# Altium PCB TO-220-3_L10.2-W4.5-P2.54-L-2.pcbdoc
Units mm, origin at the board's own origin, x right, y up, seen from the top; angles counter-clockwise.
Board outline 22.92 x 17.77 mm, 2 copper layers (Top Layer, Bottom Layer), stack 0 mm thick; 1 components, 0 nets, 3 pads, 0 vias.
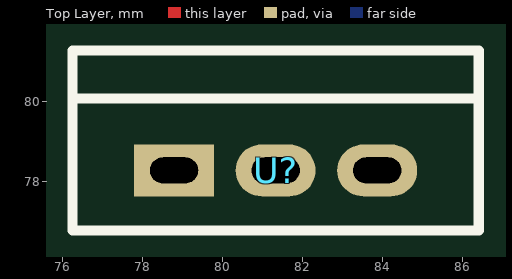
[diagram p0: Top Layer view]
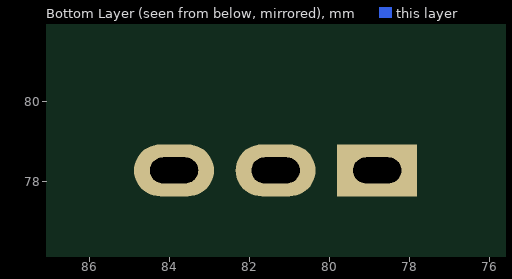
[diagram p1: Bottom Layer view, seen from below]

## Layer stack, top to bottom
Top Layer: signal copper (thickness not stored)
Bottom Layer: signal copper (thickness not stored)

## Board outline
92.77,69.85 69.85,69.85 69.85,87.622 92.77,87.622

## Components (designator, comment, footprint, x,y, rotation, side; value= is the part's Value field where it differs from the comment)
U? "" TO-220-3_L10.2-W4.5-P2.54-L-2 81.34,78.272 r0 top

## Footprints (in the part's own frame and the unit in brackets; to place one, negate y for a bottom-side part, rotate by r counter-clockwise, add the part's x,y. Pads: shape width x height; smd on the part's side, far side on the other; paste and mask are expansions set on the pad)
TO-220-3_L10.2-W4.5-P2.54-L-2 [mm]
  rect 2x1.3 hole 0.65 slot 1.2 at 0 deg: 1(-2.54,0)
  oval 2x1.3 hole 0.65 slot 1.2 at 0 deg: 2(0,0) 3(2.54,0)
  silkscreen extent -5.08,-1.5 5.08,3

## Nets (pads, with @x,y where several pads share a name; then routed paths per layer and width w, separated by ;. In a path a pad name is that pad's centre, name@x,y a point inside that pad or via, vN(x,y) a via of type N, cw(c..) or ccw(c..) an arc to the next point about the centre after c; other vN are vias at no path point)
pads on no net: U?.1 U?.2 U?.3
